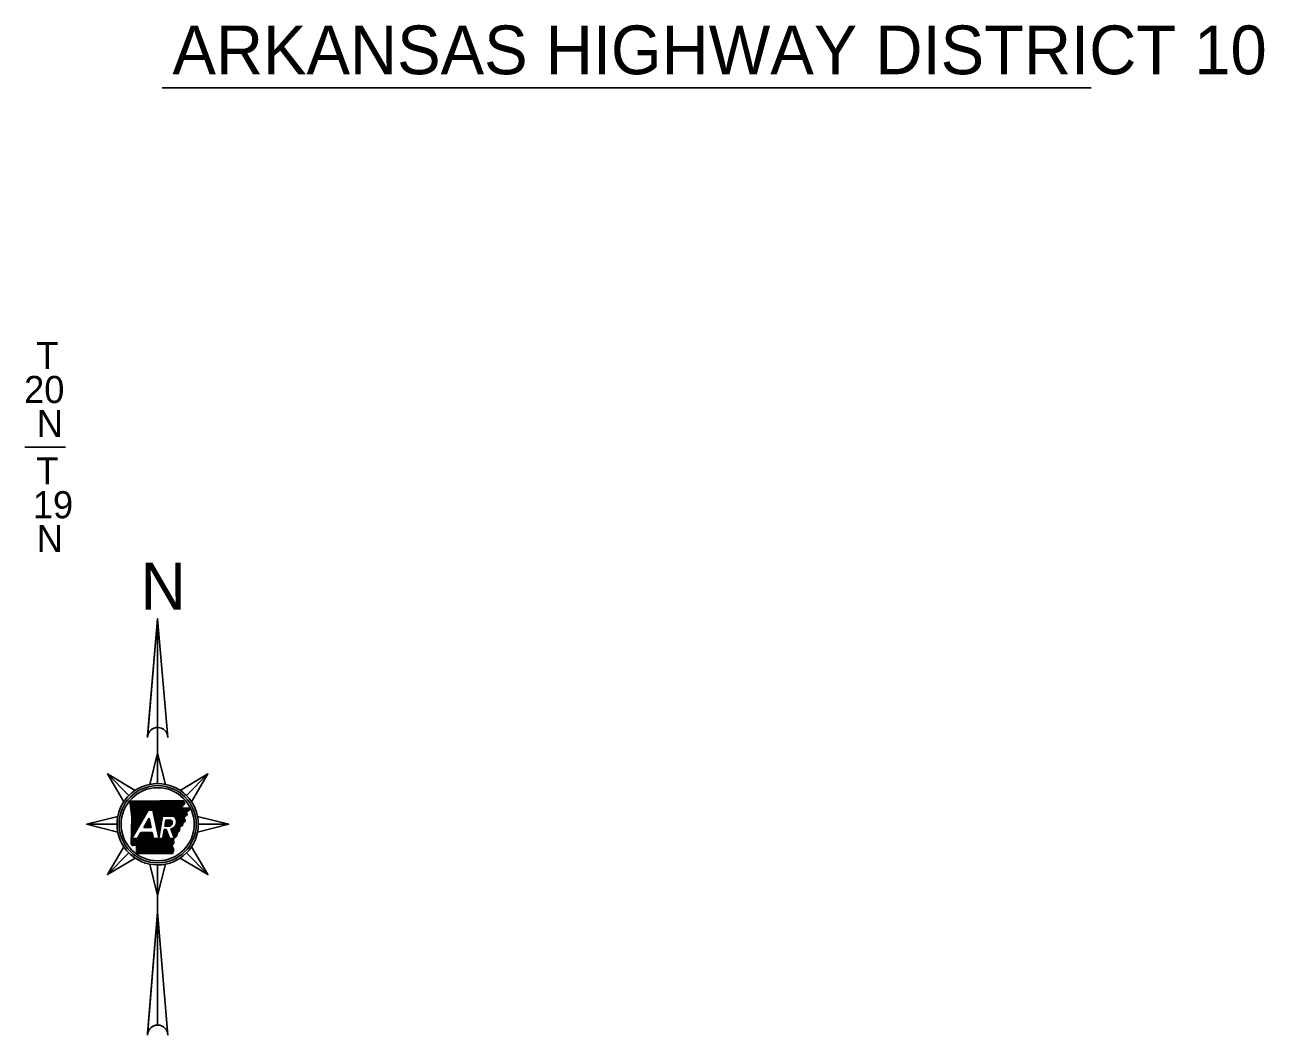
# Model space of a CAD drawing. Extents: x -549 to 3324, y -742 to 2142.
# Drawn here: x 2264 to 3179, y 570 to 1316 of the extents above; entities that cross this region are included whole.
import ezdxf

# ---------------------------------------------------------------- set-up
doc = ezdxf.new("R2010")
doc.units = 0
for name, color, linetype in [('1', 7, 'Continuous'), ('2', 7, 'Continuous'), ('Default', 7, 'Continuous'), ('Level 6', 7, 'Continuous'), ('R_Draft', 7, 'Continuous')]:
    doc.layers.add(name, color=color, linetype=linetype)

msp = doc.modelspace()

# ---------------------------------------------------------------- linework, layer by layer
at = {"layer": '1'}
msp.add_line((2365.14, 1269.04), (3050.87, 1269.04), dxfattribs=at)
at = {"layer": 'Level 6'}
msp.add_line((2263.67, 1003.85), (2293.67, 1003.85), dxfattribs=at)
at = {"layer": 'R_Draft'}
for p, q in [((2361.76, 877.06), (2354.37, 790.58)), ((2361.76, 877.06), (2361.76, 758.62)), ((2361.76, 796.81), (2361.76, 877.06)), ((2354.47, 791.79), (2354.81, 792.12)), ((2354.51, 792.25), (2355.2, 792.93)), ((2361.76, 777.85), (2355.92, 754.77)), ((2361.76, 755.35), (2361.76, 777.85)), ((2324.64, 762.47), (2340.55, 746.56)), ((2340.55, 746.56), (2324.64, 762.47)), ((2324.64, 762.47), (2336.82, 742.02)), ((2398.88, 762.47), (2378.44, 750.28)), ((2382.97, 746.56), (2398.88, 762.47)), ((2382.97, 746.56), (2398.88, 762.47)), ((2341.31, 742.26), (2341.58, 742.52)), ((2341.41, 741.5), (2342.42, 742.52)), ((2341.5, 740.75), (2343.27, 742.52)), ((2341.59, 739.99), (2344.12, 742.52)), ((2341.69, 739.24), (2344.97, 742.52)), ((2341.78, 738.48), (2345.82, 742.52)), ((2341.88, 737.73), (2346.66, 742.52)), ((2341.97, 736.97), (2347.51, 742.52)), ((2342.06, 736.22), (2348.36, 742.52)), ((2342.16, 735.46), (2349.21, 742.52)), ((2342.25, 734.71), (2350.06, 742.51)), ((2342.35, 733.96), (2350.9, 742.51)), ((2342.44, 733.2), (2351.75, 742.51)), ((2342.53, 732.45), (2352.6, 742.51)), ((2342.56, 723.99), (2361.1, 742.53)), ((2342.59, 724.87), (2360.25, 742.53)), ((2342.62, 725.74), (2359.4, 742.53)), ((2342.63, 731.69), (2353.45, 742.51)), ((2342.65, 726.62), (2358.55, 742.52)), ((2342.68, 727.5), (2357.7, 742.52)), ((2342.71, 728.38), (2356.85, 742.52)), ((2342.72, 730.94), (2354.3, 742.52)), ((2342.74, 729.26), (2356, 742.52)), ((2342.77, 730.13), (2355.15, 742.52)), ((2355.16, 735.74), (2361.95, 742.53)), ((2356.01, 735.74), (2362.8, 742.53)), ((2356.86, 735.74), (2363.66, 742.54)), ((2357.71, 735.74), (2364.52, 742.55)), ((2358.24, 735.42), (2365.38, 742.57)), ((2358.39, 734.72), (2366.24, 742.58)), ((2358.54, 734.02), (2367.11, 742.59)), ((2358.69, 733.32), (2367.97, 742.61)), ((2358.83, 732.63), (2368.83, 742.62)), ((2358.98, 731.93), (2369.69, 742.63)), ((2359.13, 731.23), (2370.55, 742.65)), ((2359.28, 730.53), (2371.42, 742.66)), ((2359.43, 729.83), (2372.28, 742.67)), ((2359.58, 729.13), (2373.14, 742.69)), ((2359.73, 728.43), (2374, 742.7)), ((2359.88, 727.73), (2374.86, 742.72)), ((2360.03, 727.03), (2375.73, 742.73)), ((2360.18, 726.34), (2376.6, 742.75)), ((2366.08, 731.38), (2377.47, 742.77)), ((2366.92, 731.38), (2378.33, 742.79)), ((2367.77, 731.38), (2379.2, 742.81)), ((2368.62, 731.38), (2380.07, 742.83)), ((2369.47, 731.38), (2380.94, 742.85)), ((2370.32, 731.38), (2381.13, 742.19)), ((2371.17, 731.38), (2381.54, 741.75)), ((2342.5, 722.23), (2352.87, 732.61)), ((2342.53, 723.11), (2353.98, 734.56)), ((2342.81, 714.84), (2354.65, 735.74)), ((2354.65, 735.74), (2358.17, 735.74)), ((2372.02, 731.38), (2381.65, 741.02)), ((2372.86, 731.38), (2379.71, 738.23)), ((2373.63, 731.3), (2379.55, 737.21)), ((2374.1, 730.92), (2380.44, 737.26)), ((2374.51, 730.48), (2381.33, 737.31)), ((2374.88, 730), (2382.23, 737.35)), ((2375.19, 729.47), (2383.12, 737.4)), ((2375.45, 728.88), (2384.02, 737.44)), ((2375.59, 725.62), (2383.29, 733.32)), ((2375.65, 728.23), (2384.82, 737.4)), ((2375.76, 727.49), (2385.22, 736.95)), ((2375.77, 726.65), (2383.19, 734.08)), ((2382.34, 731.53), (2383.39, 732.57)), ((2384.84, 735.72), (2385.62, 736.5)), ((2309.26, 725.35), (2331.76, 725.35)), ((2331.76, 725.35), (2309.26, 725.35)), ((2309.26, 725.35), (2332.33, 719.51)), ((2342.36, 717.85), (2347.34, 722.82)), ((2342.39, 718.72), (2348.44, 724.78)), ((2342.42, 719.6), (2349.55, 726.74)), ((2342.45, 720.48), (2350.66, 728.69)), ((2342.47, 721.36), (2351.77, 730.65)), ((2351.52, 723.04), (2355.39, 729.88)), ((2351.52, 723.04), (2356.86, 723.04)), ((2351.56, 723.04), (2355.92, 727.4)), ((2352.41, 723.04), (2356.07, 726.7)), ((2352.58, 724.9), (2355.77, 728.1)), ((2353.26, 723.04), (2356.22, 726.01)), ((2353.68, 726.86), (2355.62, 728.8)), ((2354.11, 723.04), (2356.37, 725.31)), ((2354.79, 728.82), (2355.47, 729.5)), ((2354.96, 723.04), (2356.52, 724.61)), ((2355.8, 723.04), (2356.67, 723.91)), ((2356.65, 723.04), (2356.82, 723.21)), ((2360.33, 725.64), (2365.15, 730.45)), ((2360.48, 724.94), (2364.97, 729.42)), ((2360.63, 724.24), (2364.79, 728.4)), ((2360.78, 723.54), (2364.61, 727.37)), ((2360.93, 722.84), (2364.43, 726.34)), ((2361.08, 722.14), (2364.25, 725.31)), ((2361.23, 721.44), (2364.07, 724.29)), ((2361.38, 720.74), (2363.89, 723.26)), ((2365.31, 731.38), (2373.53, 731.38)), ((2367.09, 723.97), (2370.62, 723.97)), ((2367.1, 723.97), (2371.56, 728.43)), ((2367.27, 724.99), (2370.71, 728.43)), ((2367.45, 726.02), (2369.86, 728.43)), ((2367.63, 727.04), (2369.02, 728.43)), ((2367.81, 728.07), (2368.17, 728.43)), ((2367.87, 728.43), (2371.73, 728.43)), ((2367.95, 723.97), (2372.03, 728.05)), ((2368.79, 723.97), (2372.32, 727.49)), ((2369.64, 723.97), (2372.48, 726.8)), ((2370.49, 723.97), (2372.4, 725.88)), ((2372.09, 720.42), (2381.49, 729.83)), ((2372.32, 719.8), (2381.65, 729.14)), ((2372.55, 719.18), (2381.81, 728.45)), ((2372.77, 718.56), (2381.97, 727.76)), ((2373, 717.94), (2378.09, 723.03)), ((2374.85, 724.04), (2381.34, 730.52)), ((2379.07, 724.01), (2380.26, 725.2)), ((2414.26, 725.35), (2391.19, 731.19)), ((2391.76, 725.35), (2414.26, 725.35)), ((2391.76, 725.35), (2414.26, 725.35)), ((2342.14, 710.84), (2346.14, 714.84)), ((2342.15, 711.7), (2345.29, 714.84)), ((2342.18, 712.58), (2344.44, 714.84)), ((2342.21, 713.46), (2343.59, 714.84)), ((2342.24, 714.34), (2342.91, 715)), ((2342.27, 715.21), (2344.01, 716.96)), ((2342.3, 716.09), (2345.12, 718.91)), ((2342.33, 716.97), (2346.23, 720.87)), ((2342.45, 710.31), (2351.37, 719.22)), ((2346.88, 714.84), (2342.81, 714.84)), ((2342.96, 709.96), (2352.22, 719.22)), ((2343.57, 709.72), (2353.07, 719.22)), ((2344.58, 709.88), (2353.92, 719.22)), ((2345.44, 709.9), (2354.77, 719.22)), ((2346.1, 709.71), (2355.62, 719.22)), ((2346.13, 708.04), (2357.31, 719.22)), ((2346.13, 708.89), (2356.46, 719.22)), ((2346.14, 707.2), (2357.76, 718.82)), ((2346.14, 706.35), (2357.91, 718.12)), ((2346.14, 705.51), (2358.06, 717.42)), ((2346.14, 704.66), (2358.21, 716.73)), ((2346.16, 703.82), (2358.36, 716.03)), ((2349.36, 719.22), (2346.88, 714.84)), ((2347, 703.82), (2358.51, 715.33)), ((2347.84, 716.54), (2350.52, 719.22)), ((2347.85, 703.82), (2358.87, 714.84)), ((2348.7, 703.82), (2359.71, 714.84)), ((2348.95, 718.49), (2349.68, 719.22)), ((2357.67, 719.22), (2349.36, 719.22)), ((2349.54, 703.82), (2360.56, 714.84)), ((2350.39, 703.82), (2361.41, 714.84)), ((2351.24, 703.82), (2362.26, 714.84)), ((2352.09, 703.82), (2363.11, 714.84)), ((2352.93, 703.81), (2363.96, 714.84)), ((2353.78, 703.81), (2364.81, 714.84)), ((2354.63, 703.81), (2369.22, 718.41)), ((2355.47, 703.81), (2369.45, 717.79)), ((2356.32, 703.81), (2369.68, 717.17)), ((2357.17, 703.81), (2369.91, 716.55)), ((2358.02, 703.81), (2370.14, 715.93)), ((2365.5, 714.84), (2358.61, 714.84)), ((2358.86, 703.8), (2370.37, 715.31)), ((2359.71, 703.8), (2370.75, 714.84)), ((2360.56, 703.8), (2371.59, 714.84)), ((2361.4, 703.8), (2372.44, 714.84)), ((2361.53, 720.04), (2363.71, 722.23)), ((2361.68, 719.35), (2363.53, 721.2)), ((2361.83, 718.65), (2363.35, 720.18)), ((2361.98, 717.95), (2363.18, 719.15)), ((2362.13, 717.25), (2363, 718.12)), ((2362.25, 703.8), (2373.29, 714.84)), ((2362.28, 716.55), (2362.82, 717.09)), ((2362.42, 715.85), (2362.64, 716.06)), ((2363.1, 703.8), (2373.57, 714.27)), ((2365.65, 715.68), (2368.99, 719.03)), ((2365.83, 716.71), (2368.76, 719.64)), ((2366.01, 717.73), (2368.54, 720.26)), ((2366.18, 718.76), (2368.31, 720.88)), ((2366.36, 719.79), (2368.06, 721.49)), ((2366.54, 720.82), (2367.21, 721.49)), ((2368.08, 721.49), (2366.66, 721.49)), ((2370.54, 714.84), (2368.08, 721.49)), ((2374.15, 714.84), (2370.54, 714.84)), ((2371.56, 721.84), (2374.15, 714.84)), ((2371.63, 721.66), (2371.89, 721.92)), ((2371.86, 721.04), (2373.47, 722.66)), ((2373.23, 717.32), (2378, 722.09)), ((2373.46, 716.7), (2377.9, 721.15)), ((2373.69, 716.09), (2376.29, 718.69)), ((2373.92, 715.47), (2375.93, 717.48)), ((2363.95, 703.8), (2373.61, 713.46)), ((2364.79, 703.79), (2373.65, 712.65)), ((2365.64, 703.79), (2373.69, 711.84)), ((2366.49, 703.79), (2372.3, 709.6)), ((2367.33, 703.79), (2372.56, 709.01)), ((2368.18, 703.79), (2372.82, 708.43)), ((2369.03, 703.79), (2373.08, 707.84)), ((2369.88, 703.79), (2373.34, 707.25)), ((2370.72, 703.78), (2373.56, 706.62)), ((2371.57, 703.78), (2373.18, 705.39)), ((2398.88, 688.22), (2386.7, 708.67)), ((2324.64, 688.22), (2340.55, 704.13)), ((2340.55, 704.13), (2324.64, 688.22)), ((2324.64, 688.22), (2345.08, 700.41)), ((2361.76, 672.85), (2367.6, 695.92)), ((2372.42, 703.78), (2372.79, 704.16)), ((2382.97, 704.13), (2398.88, 688.22)), ((2382.97, 704.13), (2398.88, 688.22)), ((2361.76, 695.35), (2361.76, 695.35)), ((2361.76, 695.35), (2361.76, 599.31)), ((2361.76, 695.35), (2361.76, 672.85)), ((2361.76, 660.31), (2354.36, 570.79)), ((2361.76, 577.06), (2361.76, 660.31))]:
    msp.add_line(p, q, dxfattribs=at)
for points in [[(2369.26, 789.31), (2361.76, 877.06), (2354.26, 789.31)], [(2355.92, 754.77), (2361.76, 777.85), (2367.6, 754.77)], [(2336.82, 742.02), (2324.64, 762.47), (2345.08, 750.28)], [(2378.44, 750.28), (2398.88, 762.47), (2386.7, 742.02)], [(2341.28, 742.52), (2352.99, 742.51), (2363.26, 742.53), (2375.38, 742.72), (2380.99, 742.85)], [(2342.13, 710.85), (2342.78, 730.49), (2341.28, 742.52)], [(2358.17, 735.74), (2362.52, 715.4), (2365.31, 731.38)], [(2384.67, 737.47), (2385.69, 736.42), (2383.16, 734.34), (2383.43, 732.24), (2381.27, 730.82), (2382.01, 727.59), (2380.34, 726.07), (2380.19, 724.41), (2378.16, 723.68), (2377.84, 720.56), (2376.38, 719), (2375.68, 716.64), (2373.55, 714.7), (2373.72, 711.27), (2372.27, 709.65), (2373.59, 706.71), (2372.68, 703.78)], [(2379.26, 737.2), (2384.75, 737.48)], [(2332.33, 719.51), (2309.26, 725.35), (2332.33, 731.19)], [(2355.39, 729.88), (2356.86, 723.04)], [(2367.09, 723.97), (2367.87, 728.43)], [(2391.19, 731.19), (2414.26, 725.35), (2391.19, 719.51)], [(2358.61, 714.84), (2357.67, 719.22)], [(2366.66, 721.49), (2365.5, 714.84)], [(2345.08, 700.41), (2324.64, 688.22), (2336.82, 708.67)], [(2372.68, 703.78), (2346.14, 703.82), (2346.13, 709.68)], [(2386.7, 708.67), (2398.88, 688.22), (2378.44, 700.41)], [(2367.6, 695.92), (2361.76, 672.85), (2355.92, 695.92)], [(2369.26, 569.56), (2361.76, 660.31), (2354.26, 569.56)]]:
    msp.add_lwpolyline(points, dxfattribs=at)
for radius in [30, 28.5, 27]:
    msp.add_circle((2361.76, 725.35), radius, dxfattribs=at)
for centre, radius, start, end in [((2361.76, 789.31), 7.5, 0, 180), ((2361.76, 789.31), 7.5, 90, 170.22959), ((2361.76, 725.35), 30, 90, 101.22909), ((2361.76, 725.35), 30, 45, 56.22909), ((2361.76, 725.35), 30, 135, 146.22909), ((2361.76, 725.35), 30, 180, 191.22909), ((2369.77, 726.55), 2.72, 288.12683, 43.89016), ((2370.47, 727.04), 5.31, 281.86262, 54.87052), ((2361.76, 725.35), 30, 0, 11.22909), ((2361.76, 725.35), 30, 315, 326.22909), ((2361.76, 725.35), 30, 225, 236.22909), ((2361.76, 725.35), 30, 270, 281.22909), ((2361.76, 569.56), 7.5, 0, 180), ((2361.76, 569.56), 7.5, 90, 170.5511)]:
    msp.add_arc(centre, radius, start, end, dxfattribs=at)
for points in [[(2380.99, 742.85), (2381.03, 742.53), (2381.13, 742.37), (2381.15, 742.06), (2381.27, 741.93), (2381.48, 741.8), (2381.67, 741.59), (2381.71, 741.35), (2381.65, 741.09), (2381.64, 740.81), (2381.61, 740.57), (2381.57, 740.34), (2381.39, 740.16), (2381.23, 740.03), (2381.07, 739.88), (2380.97, 739.72), (2380.78, 739.54), (2380.59, 739.36), (2380.44, 739.2), (2380.29, 739), (2380.21, 738.78), (2380.05, 738.62), (2379.92, 738.47), (2379.74, 738.28), (2379.66, 738.08), (2379.49, 737.86), (2379.45, 737.64), (2379.34, 737.47), (2379.34, 737.44)], [(2346.13, 709.68), (2346.16, 709.67), (2346.02, 709.76), (2345.83, 709.86), (2345.62, 709.87), (2345.35, 709.91), (2345.13, 709.93), (2344.9, 710.08), (2344.65, 709.92), (2344.38, 709.8), (2344.22, 709.94), (2344.01, 709.85), (2343.86, 709.89), (2343.61, 709.72), (2343.37, 709.78), (2343.2, 709.73), (2342.98, 709.74), (2342.94, 709.99), (2342.73, 710.02), (2342.55, 710.12), (2342.42, 710.38), (2342.34, 710.57), (2342.13, 710.85)]]:
    msp.add_spline(points, degree=3, dxfattribs=at)

# ---------------------------------------------------------------- texts
at = {"layer": '2'}
msp.add_text('ARKANSAS HIGHWAY DISTRICT 10', height=36, dxfattribs=at).set_placement((2372.67, 1279.17))
at = {"layer": 'Default'}
for s, p in [('T', (2272.13, 1061.43)), ('20', (2263.16, 1036.39)), ('N', (2272.45, 1011.35)), ('T', (2272.13, 976.35)), ('19', (2269.61, 951.31)), ('N', (2272.45, 926.27))]:
    msp.add_text(s, height=20, dxfattribs=at).set_placement(p)
at = {"layer": 'R_Draft'}
for s, height, p in [('N', 34.62, (2349.11, 883.87)), ('DWB 7-27-17', 0.5833, (2359.92, 697.85))]:
    msp.add_text(s, height=height, dxfattribs=at).set_placement(p)

doc.saveas('drawing.dxf')
